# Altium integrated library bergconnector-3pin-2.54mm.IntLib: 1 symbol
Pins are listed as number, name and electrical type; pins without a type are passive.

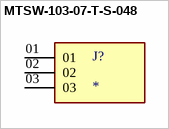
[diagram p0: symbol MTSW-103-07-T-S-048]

## MTSW-103-07-T-S-048
designator J?
MP: MTSW-103-07-T-S-048
footprint SAMTEC_MTSW-103-07-T-S-048
pins: 01, 02, 03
